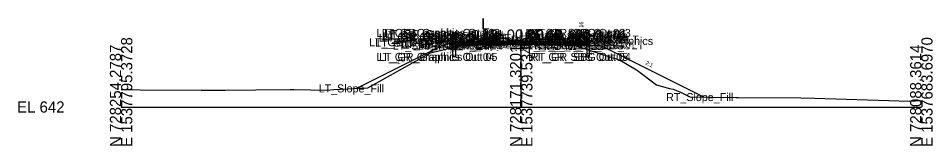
# Model space of a CAD drawing. Extents: x -26 to 1203, y -10 to 9522.
# Drawn here: x -25.7 to 202.8, y 8990.3 to 9022.2 of the extents above; entities that cross this region are included whole.
import ezdxf

# ---------------------------------------------------------------- set-up
doc = ezdxf.new("R2010")
doc.units = 0
for name, color, linetype in [('Default', 7, 'Continuous'), ('Exist Cross Section Cell', 7, 'Continuous'), ('Exist XS Center Line Elevation Label', 7, 'Continuous'), ('Exist XS Ground Line', 7, 'Continuous'), ('Old_Level_63', 7, 'Continuous'), ('Prop CMT Conc Surface', 7, 'Continuous'), ('Prop CMT Concrete Structures', 7, 'Continuous'), ('Prop CMT Guardrail Graphics', 7, 'Continuous'), ('Prop CMT Guardrail SBG', 7, 'Continuous'), ('Prop CMT Pvmt Course 1', 7, 'Continuous'), ('Prop CMT Pvmt Course 2', 7, 'Continuous'), ('Prop CMT Pvmt Course 3', 7, 'Continuous'), ('Prop CMT Pvmt Course SBG', 7, 'Continuous'), ('Prop CMT Pvmt Surface', 7, 'Continuous'), ('Prop CMT Pvmt Surface Overlay', 7, 'Continuous'), ('Prop CMT Pvmt Surface Shoulder', 7, 'Continuous'), ('Prop CMT Shld Paved Course 1', 7, 'Continuous'), ('Prop CMT Shld Paved Course 2', 7, 'Continuous'), ('Prop CMT Shld Paved Course 3', 7, 'Continuous'), ('Prop CMT Slope Grass', 7, 'Continuous'), ('Prop CMT Subgrade Earthwork', 7, 'Continuous'), ('Prop Superelevation  Arrow CELL', 7, 'Continuous'), ('Prop XS EOT Tick Mark', 7, 'Continuous'), ('Prop XS Hydro Elevations', 7, 'Continuous'), ('Prop XS SE Text', 7, 'Continuous'), ('Prop XS Side Slope Text', 7, 'Continuous')]:
    doc.layers.add(name, color=color, linetype=linetype)

msp = doc.modelspace()

# ---------------------------------------------------------------- linework, layer by layer
at = {"layer": 'Exist Cross Section Cell'}
for p, q in [((100, 9000), (100, 9019.41)), ((0, 9000), (100, 9000)), ((100, 9000), (200, 9000))]:
    msp.add_line(p, q, dxfattribs=at)
at = {"layer": 'Exist XS Ground Line'}
msp.add_lwpolyline([(0, 9004.37), (2.74, 9004.36), (4.75, 9004.32), (20.03, 9004.21), (23.14, 9004.22), (24.76, 9004.2), (25.38, 9004.23), (26.03, 9004.22), (33.69, 9004.28), (42.28, 9004.41), (43.26, 9004.35), (51.38, 9004.19), (53.19, 9004.35), (61.7, 9004.8), (76.59, 9013.17), (77.11, 9013.45), (77.34, 9013.53), (85.96, 9015.61), (87.54, 9015.77), (99.26, 9015.92), (100, 9015.93), (100.48, 9015.94), (101.56, 9015.92), (111.97, 9015.78), (112.7, 9015.74), (114.14, 9015.15), (124.73, 9011.71), (128.84, 9009.26), (129.09, 9009.11), (133.82, 9005.53), (137.02, 9004.67), (138.01, 9004.48), (139.68, 9003.81), (142.11, 9002.54), (153.6, 9002.36), (153.88, 9002.36), (154.09, 9002.36), (154.34, 9002.37), (169.92, 9002.33), (173.2, 9002.2), (181.33, 9001.94), (197.02, 9001.47), (200, 9001.59)], dxfattribs=at)
at = {"layer": 'Prop CMT Conc Surface'}
msp.add_lwpolyline([(113.16, 9016.26), (115.5, 9016.16), (116.16, 9016.51)], dxfattribs=at)
at = {"layer": 'Prop CMT Concrete Structures'}
for points in [[(113.16, 9016.26), (115.5, 9016.16), (116.16, 9016.51)], [(113.16, 9015.84), (113.16, 9016.26)], [(116.16, 9015.84), (113.16, 9015.84)], [(116.16, 9016.51), (116.16, 9015.84)]]:
    msp.add_lwpolyline(points, dxfattribs=at)
at = {"layer": 'Prop CMT Guardrail Graphics'}
for points in [[(82.9, 9012.54), (82.9, 9018.54)], [(82.9, 9018.54), (84.23, 9018.54), (84.5, 9018.25)], [(84.5, 9018.25), (84.23, 9017.96)], [(84.23, 9017.96), (84.5, 9017.67)], [(84.5, 9017.67), (84.23, 9017.38), (83.57, 9017.38)], [(83.57, 9017.38), (83.57, 9012.54)], [(83.57, 9012.54), (82.9, 9012.54)]]:
    msp.add_lwpolyline(points, dxfattribs=at)
at = {"layer": 'Prop CMT Guardrail SBG'}
for points in [[(117.1, 9018.54), (115.77, 9018.54), (115.5, 9018.25)], [(115.5, 9018.25), (115.77, 9017.96)], [(115.77, 9017.96), (115.5, 9017.67)], [(117.1, 9012.54), (117.1, 9018.54)], [(115.5, 9017.67), (115.77, 9017.38), (116.43, 9017.38)], [(116.43, 9017.38), (116.43, 9012.54)], [(116.43, 9012.54), (117.1, 9012.54)]]:
    msp.add_lwpolyline(points, dxfattribs=at)
at = {"layer": 'Prop CMT Pvmt Course 1'}
for points in [[(100, 9016.52), (89, 9016.3)], [(89, 9016.3), (89, 9016.05)], [(89, 9016.05), (100, 9016.27)], [(100, 9016.27), (100, 9016.52)], [(100, 9016.52), (111, 9016.3)], [(100, 9016.27), (100, 9016.52)], [(100, 9016.27), (100, 9016.27), (100, 9016.27)], [(111, 9016.05), (100, 9016.27)], [(100, 9016.27), (100, 9016.27), (100, 9016.27)], [(111, 9016.3), (111, 9016.05)]]:
    msp.add_lwpolyline(points, dxfattribs=at)
at = {"layer": 'Prop CMT Pvmt Course 2'}
for points in [[(100, 9016.27), (89, 9016.05)], [(89, 9015.84), (100, 9016.06)], [(89, 9016.05), (89, 9015.84)], [(100, 9016.06), (100, 9016.27)], [(100, 9016.06), (100, 9016.27)], [(100, 9016.27), (111, 9016.05)], [(111, 9015.84), (100, 9016.06)], [(111, 9016.05), (111, 9015.84)]]:
    msp.add_lwpolyline(points, dxfattribs=at)
at = {"layer": 'Prop CMT Pvmt Course 3'}
for points in [[(100, 9016.06), (89, 9015.84)], [(89, 9015.84), (89, 9015.47)], [(89, 9015.47), (100, 9015.69)], [(100, 9015.69), (100, 9016.06)], [(100, 9016.06), (111, 9015.84)], [(100, 9015.69), (100, 9016.06)], [(111, 9015.47), (100, 9015.69)], [(111, 9015.84), (111, 9015.47)]]:
    msp.add_lwpolyline(points, dxfattribs=at)
at = {"layer": 'Prop CMT Pvmt Course SBG'}
for points in [[(113.16, 9015.84), (116.16, 9015.84), (116.66, 9015.84), (117.08, 9015.42)], [(113.16, 9015.42), (113.16, 9015.84)], [(117.08, 9015.42), (113.16, 9015.42)]]:
    msp.add_lwpolyline(points, dxfattribs=at)
at = {"layer": 'Prop CMT Pvmt Surface'}
for points in [[(100, 9016.52), (89, 9016.3)], [(100, 9016.52), (111, 9016.3)]]:
    msp.add_lwpolyline(points, dxfattribs=at)
at = {"layer": 'Prop CMT Pvmt Surface Overlay'}
for points in [[(100, 9016.52), (89, 9016.3)], [(100, 9016.52), (111, 9016.3)]]:
    msp.add_lwpolyline(points, dxfattribs=at)
at = {"layer": 'Prop CMT Pvmt Surface Shoulder'}
for points in [[(89, 9016.3), (84.52, 9016.21)], [(111, 9016.3), (113.16, 9016.26)]]:
    msp.add_lwpolyline(points, dxfattribs=at)
at = {"layer": 'Prop CMT Shld Paved Course 1'}
for points in [[(89, 9016.3), (84.52, 9016.21), (84.26, 9015.96)], [(84.26, 9015.96), (89, 9016.05)], [(89, 9016.05), (89, 9016.3)], [(111, 9016.3), (113.16, 9016.26)], [(111, 9016.05), (111, 9016.3)], [(113.16, 9016.01), (111, 9016.05)], [(113.16, 9016.26), (113.16, 9016.01)]]:
    msp.add_lwpolyline(points, dxfattribs=at)
at = {"layer": 'Prop CMT Shld Paved Course 2'}
for points in [[(89, 9016.05), (84.26, 9015.96), (84.05, 9015.74)], [(84.05, 9015.74), (89, 9015.84)], [(89, 9015.84), (89, 9016.05)], [(111, 9016.05), (113.16, 9016.01)], [(111, 9015.84), (111, 9016.05)], [(113.16, 9015.8), (111, 9015.84)], [(113.16, 9016.01), (113.16, 9015.8)]]:
    msp.add_lwpolyline(points, dxfattribs=at)
at = {"layer": 'Prop CMT Shld Paved Course 3'}
for points in [[(84.05, 9015.74), (83.66, 9015.36)], [(89, 9015.84), (84.05, 9015.74)], [(84.05, 9015.74), (84.05, 9015.74)], [(89, 9015.47), (89, 9015.84)], [(111, 9015.84), (113.16, 9015.8)], [(111, 9015.47), (111, 9015.84)], [(113.16, 9015.8), (113.16, 9015.42)], [(83.66, 9015.36), (89, 9015.47)], [(113.16, 9015.42), (111, 9015.47)]]:
    msp.add_lwpolyline(points, dxfattribs=at)
at = {"layer": 'Prop CMT Slope Grass'}
for points in [[(81.5, 9015.97), (58.86, 9004.65)], [(84.5, 9016.21), (81.5, 9015.97)], [(84.52, 9016.21), (84.5, 9016.21)], [(116.16, 9016.51), (116.91, 9016.89), (145.74, 9002.48)]]:
    msp.add_lwpolyline(points, dxfattribs=at)
at = {"layer": 'Prop CMT Subgrade Earthwork'}
for points in [[(83.66, 9015.36), (82.94, 9016.09)], [(100, 9015.69), (89, 9015.47)], [(100, 9015.69), (111, 9015.47)], [(89, 9015.47), (83.66, 9015.36)], [(111, 9015.47), (113.16, 9015.42)], [(113.16, 9015.42), (113.16, 9015.42)], [(113.16, 9015.42), (117.08, 9015.42), (119.85, 9015.42)]]:
    msp.add_lwpolyline(points, dxfattribs=at)
at = {"layer": 'Prop Superelevation  Arrow CELL'}
for p, q in [((97.03, 9017.14), (91.03, 9017.02)), ((103.02, 9016.98), (109.02, 9016.86))]:
    msp.add_line(p, q, dxfattribs=at)
for points in [[(91.03, 9017.02), (92.52, 9017.55), (92.19, 9017.04)], [(109.02, 9016.86), (107.53, 9017.39), (107.87, 9016.88)]]:
    msp.add_lwpolyline(points, close=True, dxfattribs=at)
at = {"layer": 'Prop XS EOT Tick Mark'}
for points in [[(89, 9016.3), (89, 9017.3)], [(111, 9016.3), (111, 9017.3)]]:
    msp.add_lwpolyline(points, dxfattribs=at)

# ---------------------------------------------------------------- texts
at = {"layer": 'Default'}
msp.add_text('-', height=0.0001, dxfattribs=at).set_placement((0, 9000))
msp.add_text('-', height=0.0001, dxfattribs=at).set_placement((0, 9000))
msp.add_text('-', height=0.0001, dxfattribs=at).set_placement((0, 9000))
at = {"layer": 'Exist Cross Section Cell'}
for s, p in [('L', (90, 9019.41)), ('18+00.00 / 1', (90, 9016.61)), ('EL 642', (-26, 8998.6))]:
    msp.add_text(s, height=2.8, dxfattribs=at).set_placement(p)
for s, p in [('E 1537795.3728', (2.8, 8990)), ('E 1537739.5349', (102.8, 8990)), ('E 1537683.6970', (202.8, 8990)), ('N 728254.2787', (0, 8990)), ('N 728171.3201', (100, 8990)), ('N 728088.3614', (200, 8990))]:
    msp.add_text(s, height=2.8, rotation=90, dxfattribs=at).set_placement(p)
at = {"layer": 'Exist XS Center Line Elevation Label'}
msp.add_text('657.93', height=0.75, dxfattribs=at).set_placement((98.37, 9014.68))
at = {"layer": 'Old_Level_63'}
for s, p in [('LT_GR_Graphics Out 03', (63.8, 9017.54)), ('LT_GR_Graphics Out 06', (64.42, 9016.38)), ('LT_GR_Graphics Out 02', (65.13, 9017.54)), ('LT_GR_Graphics Out 09', (65.13, 9016.96)), ('LT_GR_Graphics Out 07', (65.13, 9016.38)), ('LT_GR_Graphics Out 08', (65.4, 9016.67)), ('LT_GR_Graphics Out 01', (65.97, 9017.25)), ('LT_TM_OEOT', (79.94, 9016.3)), ('RT_Sub_Trench_Out_DLT', (97.43, 9015.89)), ('RT_GR_SBG Out 08', (100.8, 9016.67)), ('RT_GR_SBG Out 02', (101.07, 9017.54)), ('RT_GR_SBG Out 09', (101.07, 9016.96)), ('RT_GR_SBG Out 07', (101.07, 9016.38)), ('RT_GR_SBG Out 01', (101.37, 9017.25)), ('RT_GR_SBG Out 06', (101.69, 9016.38)), ('RT_TM_OEOT', (101.9, 9016.3)), ('RT_GR_SBG Out 03', (102.41, 9017.54)), ('RT_GS_OS_CTL', (106.23, 9015.89)), ('LT_GS_OS_GR_Face_Graphics', (61.96, 9015.21)), ('LT_Sub_Trench_Out_DLT', (63.51, 9015.09)), ('LT_Sub_Trench_Out', (67.87, 9014.36)), ('LT_PS3_Shelf_Out', (70.03, 9014.74)), ('LT_GS_OS_CTL', (70.87, 9014.97)), ('LT_PS3_OEOP', (74.28, 9014.74)), ('LT_PS2_OEOP', (74.5, 9014.96)), ('LT_PS1_OEOP', (75.32, 9015.21)), ('LT_Sub_OEOT', (79.08, 9014.47)), ('LT_PV2_OEOT', (79.17, 9015.05)), ('LT_PV3_OEOT', (79.17, 9014.84)), ('LT_PV1_OEOT', (79.74, 9015.3)), ('RT_PV1_OEEOP_W', (87.94, 9015.27)), ('LT_PV1_OEEOP_W', (87.98, 9015.27)), ('RT_Sub_OEEOP', (89.17, 9014.69)), ('LT_Sub_OEEOP', (89.21, 9014.69)), ('RT_PV2_OEEOP', (89.26, 9015.27)), ('RT_PV3_OEEOP', (89.26, 9015.06)), ('LT_PV2_OEEOP', (89.31, 9015.27)), ('LT_PV3_OEEOP', (89.31, 9015.06)), ('PV1_PGL_W', (92.58, 9015.27)), ('RT_GS_OS_GR_Face_Graphics', (93.57, 9015.51)), ('PV1_PGL', (94.47, 9015.52)), ('RT_Sub_OEOP_SBG', (99.57, 9014.42)), ('RT_SBG_C1 Shelf Out', (100.76, 9014.84)), ('RT_Sub_OEOT', (101.03, 9014.47)), ('RT_PV2_OEOT', (101.13, 9015.05)), ('RT_PV3_OEOT', (101.13, 9014.84)), ('RT_PV1_OEOT', (101.69, 9015.3)), ('RT_CG_Bot_IE', (103.03, 9014.84)), ('RT_Sub_OEOP', (103.22, 9014.42)), ('RT_PS2_OEOP', (103.35, 9015.01)), ('RT_PS3_OEOP', (103.35, 9014.8)), ('RT_CG_Top_Gut', (103.68, 9015.16)), ('RT_PS1_OEOP', (103.92, 9015.26)), ('RT_Sub_SBG Out', (104.21, 9014.42)), ('RT_CG_Top_BOC', (104.4, 9015.51)), ('RT_CG_Bot_BOC', (104.43, 9014.84)), ('RT_Sub_OSS_DLT', (107.21, 9014.42)), ('LT_GR_Graphics Out 04', (63.8, 9011.54)), ('LT_GR_Graphics Out 05', (64.47, 9011.54)), ('RT_GR_SBG Out 05', (101.74, 9011.54)), ('RT_GR_SBG Out 04', (102.41, 9011.54)), ('LT_Slope_Fill', (49.38, 9003.65)), ('RT_Slope_Fill', (136.21, 9001.48))]:
    msp.add_text(s, height=2, dxfattribs=at).set_placement(p)
at = {"layer": 'Prop XS Hydro Elevations'}
msp.add_text('658.16', height=1, rotation=90, dxfattribs=at).set_placement((115.5, 9017.16))
at = {"layer": 'Prop XS SE Text'}
for rotation, p in [(1.1458, (92.73, 9017.38)), (358.8542, (103.77, 9017.45))]:
    msp.add_text('0.020', height=1, rotation=rotation, dxfattribs=at).set_placement(p)
at = {"layer": 'Prop XS Side Slope Text'}
for rotation, p in [(26.5651, (69.14, 9010.63)), (333.4349, (130.95, 9010.71))]:
    msp.add_text('2:1', height=1, rotation=rotation, dxfattribs=at).set_placement(p)

doc.saveas('drawing.dxf')
